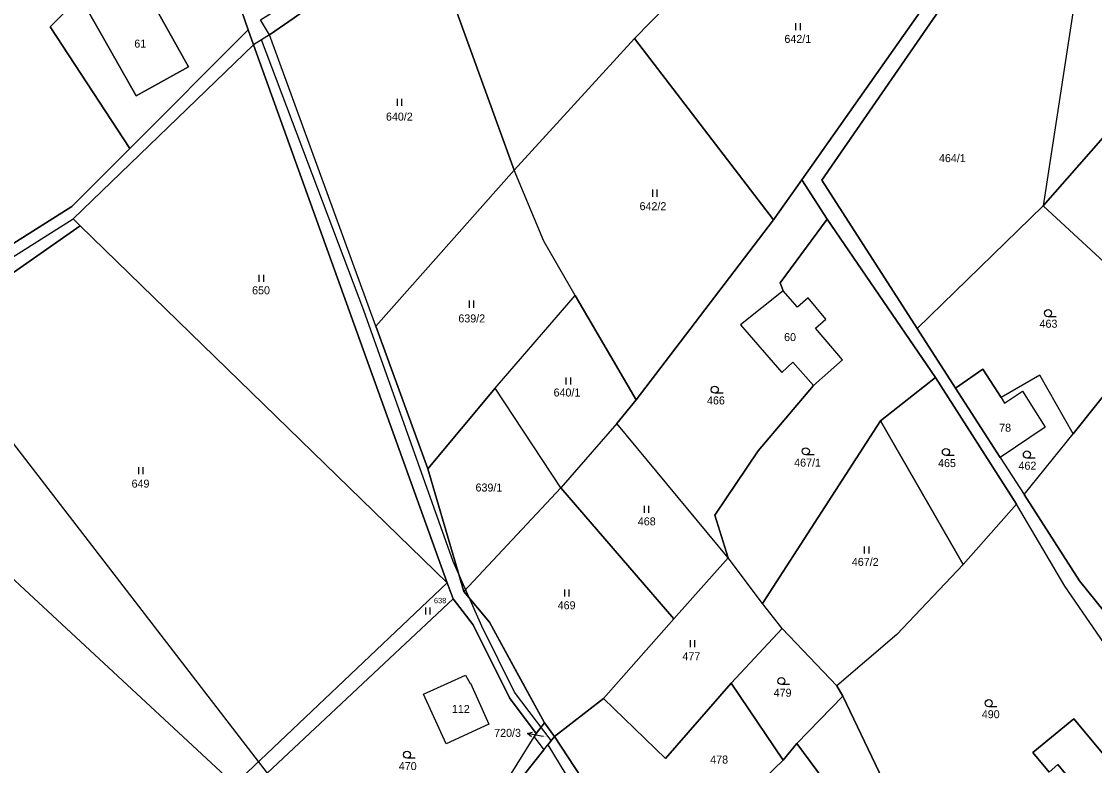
# Model space of a CAD drawing. Extents: x -590606 to -587796, y -1065936 to -1062515.
# Drawn here: x -589641.2 to -589413.2, y -1064918.8 to -1064760.8 of the extents above; entities that cross this region are included whole.
import ezdxf

# ---------------------------------------------------------------- set-up
doc = ezdxf.new("R2010")
doc.units = 0
for name, color, linetype in [('Cesty', 7, 'Continuous'), ('Parcela nároku', 7, 'Continuous'), ('Parcelní číslo', 7, 'Continuous'), ('Vnější obvod_ Studené', 7, 'Continuous'), ('Vrstva 1', 7, 'Continuous'), ('Vrstva 30', 7, 'Continuous'), ('Územní plán', 7, 'Continuous')]:
    doc.layers.add(name, color=color, linetype=linetype)

msp = doc.modelspace()

# ---------------------------------------------------------------- linework, layer by layer
at = {"layer": 'Cesty'}
msp.add_lwpolyline([(-589528.63, -1064913.52), (-589536.44, -1064903.23), (-589543.34, -1064889.26), (-589549.43, -1064875.48), (-589568.43, -1064822.17), (-589590.16, -1064764.72)], dxfattribs=at)
at = {"layer": 'Parcela nároku'}
for points in [[(-589522.89, -1064698.36), (-589513.75, -1064690.35), (-589497.56, -1064678.5), (-589496.63, -1064681.82), (-589511.03, -1064691.51), (-589528.63, -1064706.39), (-589554.07, -1064735.46), (-589571.42, -1064751.62), (-589583.26, -1064760.02), (-589588.45, -1064763.67), (-589590.38, -1064760.46), (-589573.06, -1064749.58), (-589560.8, -1064738.7), (-589530.19, -1064704.81)], [(-589378.38, -1064737.45), (-589411.5, -1064705.67), (-589425, -1064725.38), (-589416.09, -1064747.85), (-589424.1, -1064799.94), (-589411.31, -1064785.43), (-589390.57, -1064758.82)], [(-589530.55, -1064711.43), (-589504.08, -1064757.44), (-589510.92, -1064764.47), (-589536.47, -1064792.4), (-589552.16, -1064749.21), (-589553.84, -1064737.2)], [(-589605.54, -1064732.57), (-589618.13, -1064717.98), (-589627.72, -1064729.04), (-589662.24, -1064761.36), (-589694.16, -1064785.11), (-589664.99, -1064821.89), (-589630.44, -1064800.11), (-589618.14, -1064787.77), (-589635.08, -1064761.95), (-589628.69, -1064755.59), (-589628.92, -1064755.19), (-589627.45, -1064754.35)], [(-589473.46, -1064724.46), (-589449.38, -1064757.57), (-589475.36, -1064794.48), (-589481.42, -1064802.93), (-589510.92, -1064764.47), (-589504.08, -1064757.44)], [(-589447.12, -1064755.09), (-589425, -1064725.38), (-589416.09, -1064747.85), (-589424.1, -1064799.94), (-589450.87, -1064826.05), (-589471.15, -1064794.54), (-589445.45, -1064757.41)], [(-589593.02, -1064762.59), (-589597.63, -1064749.22), (-589605.54, -1064732.57), (-589627.45, -1064754.35), (-589617.78, -1064748.87), (-589613.71, -1064756.12), (-589605.65, -1064770.49), (-589616.76, -1064776.62), (-589624.91, -1064762.26), (-589628.69, -1064755.59), (-589635.08, -1064761.95), (-589618.14, -1064787.77)], [(-589583.26, -1064760.02), (-589571.42, -1064751.62), (-589554.07, -1064735.46), (-589553.84, -1064737.2), (-589552.16, -1064749.21), (-589536.47, -1064792.4), (-589565.9, -1064825.54), (-589588.45, -1064763.67)], [(-589605.65, -1064770.49), (-589613.71, -1064756.12), (-589617.78, -1064748.87), (-589627.45, -1064754.35), (-589628.92, -1064755.19), (-589628.69, -1064755.59), (-589624.91, -1064762.26), (-589616.76, -1064776.62)], [(-589593.02, -1064762.59), (-589618.14, -1064787.77), (-589630.44, -1064800.11), (-589664.99, -1064821.89), (-589669.05, -1064824.3), (-589667.75, -1064826.48), (-589630.17, -1064802.74), (-589591.88, -1064765.77)], [(-589550.69, -1064880.06), (-589591.88, -1064765.77), (-589630.17, -1064802.74), (-589628.67, -1064804.2)], [(-589510.92, -1064764.47), (-589481.42, -1064802.93), (-589510.57, -1064841.17), (-589523.5, -1064819.01), (-589530.21, -1064807.51), (-589536.47, -1064792.4)], [(-589411.31, -1064785.43), (-589424.1, -1064799.94), (-589398.19, -1064823.87), (-589385.83, -1064808.46)], [(-589523.5, -1064819.01), (-589530.21, -1064807.51), (-589536.47, -1064792.4), (-589565.9, -1064825.54), (-589554.84, -1064855.85), (-589540.51, -1064838.69)], [(-589479.64, -1064835.38), (-589477.29, -1064833.19), (-589472.89, -1064838.14), (-589484.61, -1064851.97), (-589493.85, -1064865.65), (-589491.05, -1064874.72), (-589514.68, -1064846.22), (-589510.57, -1064841.17), (-589481.42, -1064802.93), (-589475.36, -1064794.48), (-589469.95, -1064802.77), (-589480, -1064816.34), (-589479.3, -1064817.99), (-589488.43, -1064825.26)], [(-589424.1, -1064799.94), (-589398.19, -1064823.87), (-589417.74, -1064848.39), (-589424.79, -1064835.96), (-589433.05, -1064840.7), (-589436.92, -1064834.69), (-589442.72, -1064838.68), (-589450.87, -1064826.05)], [(-589672.56, -1064837.8), (-589664.19, -1064828.97), (-589628.67, -1064804.2), (-589550.69, -1064880.06), (-589595.93, -1064922.82), (-589688.26, -1064837.19), (-589677.04, -1064831.33)], [(-589630.17, -1064802.74), (-589628.67, -1064804.2), (-589664.19, -1064828.97), (-589672.56, -1064837.8), (-589677.04, -1064831.33), (-589667.75, -1064826.48)], [(-589469.95, -1064802.77), (-589447, -1064836.46), (-589458.66, -1064845.6), (-589483.72, -1064884.38), (-589491.05, -1064874.72), (-589493.85, -1064865.65), (-589484.61, -1064851.97), (-589472.89, -1064838.14), (-589466.74, -1064832.65), (-589472.45, -1064825.98), (-589470.28, -1064824.07), (-589474.03, -1064819.53), (-589476.31, -1064821.48), (-589479.3, -1064817.99), (-589480, -1064816.34)], [(-589466.74, -1064832.65), (-589472.45, -1064825.98), (-589470.28, -1064824.07), (-589474.03, -1064819.53), (-589476.31, -1064821.48), (-589479.3, -1064817.99), (-589488.43, -1064825.26), (-589479.64, -1064835.38), (-589477.29, -1064833.19), (-589472.89, -1064838.14)], [(-589540.51, -1064838.69), (-589523.5, -1064819.01), (-589510.57, -1064841.17), (-589514.68, -1064846.22), (-589526.55, -1064859.84)], [(-589417.74, -1064848.39), (-589398.19, -1064823.87), (-589382.87, -1064851.27), (-589357.44, -1064856.96), (-589360.23, -1064861.82), (-589364.23, -1064868.85), (-589369.41, -1064877.92), (-589371.23, -1064875.18), (-589374.55, -1064880.76), (-589389.82, -1064866.59), (-589402.24, -1064899.51), (-589405.49, -1064893.12), (-589416.34, -1064879.6), (-589428.15, -1064861.27)], [(-589458.66, -1064845.6), (-589447, -1064836.46), (-589429.73, -1064863.35), (-589441.1, -1064876.11)], [(-589433.05, -1064840.7), (-589432.28, -1064841.89), (-589428.45, -1064839.33), (-589423.69, -1064847), (-589433.24, -1064853.38), (-589442.72, -1064838.68), (-589436.92, -1064834.69)], [(-589424.79, -1064835.96), (-589433.05, -1064840.7), (-589432.28, -1064841.89), (-589428.45, -1064839.33), (-589423.69, -1064847), (-589433.24, -1064853.38), (-589428.15, -1064861.27), (-589417.74, -1064848.39)], [(-589738.8, -1064868.37), (-589722.06, -1064859.86), (-589695.94, -1064842.79), (-589696.42, -1064842.01), (-589688.26, -1064837.19), (-589595.93, -1064922.82), (-589621.92, -1064947.69), (-589643.25, -1064958.89)], [(-589540.51, -1064838.69), (-589554.84, -1064855.85), (-589547.18, -1064881.85), (-589526.55, -1064859.84)], [(-589458.66, -1064845.6), (-589441.1, -1064876.11), (-589455.18, -1064891.01), (-589467.9, -1064901.87), (-589479.54, -1064889.74), (-589483.72, -1064884.38)], [(-589491.05, -1064874.72), (-589514.68, -1064846.22), (-589526.55, -1064859.84), (-589502.56, -1064887.68)], [(-589502.56, -1064887.68), (-589526.55, -1064859.84), (-589547.18, -1064881.85), (-589541.76, -1064888.37), (-589530.03, -1064909.73), (-589527.95, -1064912.63), (-589517.52, -1064904.58)], [(-589419.51, -1064880.71), (-589429.73, -1064863.35), (-589441.1, -1064876.11), (-589455.18, -1064891.01), (-589467.9, -1064901.87), (-589466.69, -1064904.1), (-589451.25, -1064936.39), (-589448.63, -1064940.01), (-589428.23, -1064968.24), (-589418.35, -1064953.57), (-589406.51, -1064936.87), (-589411.18, -1064930.48), (-589420.99, -1064918.63), (-589422.85, -1064920.26), (-589426.28, -1064916.08), (-589417.57, -1064908.93), (-589404.77, -1064924.29), (-589403.91, -1064923.64), (-589400.68, -1064928.65), (-589394.5, -1064919.94), (-589399.91, -1064912.39), (-589408.85, -1064896.13)], [(-589479.54, -1064889.74), (-589483.72, -1064884.38), (-589491.05, -1064874.72), (-589502.56, -1064887.68), (-589517.52, -1064904.58), (-589504.34, -1064917.35), (-589490.4, -1064901.33)], [(-589643.25, -1064958.89), (-589718.4, -1064982.65), (-589738.86, -1064988.82), (-589792.56, -1065010.99), (-589790.16, -1065012.34), (-589739.56, -1064991.1), (-589640.21, -1064959.48), (-589620.7, -1064948.96), (-589616.14, -1064944.82), (-589588.94, -1064920.46), (-589549.47, -1064883.45), (-589550.69, -1064880.06), (-589595.93, -1064922.82), (-589621.92, -1064947.69)], [(-589531.78, -1064912.02), (-589537.45, -1064904.41), (-589545.23, -1064888.95), (-589549.47, -1064883.45), (-589588.94, -1064920.46), (-589561.54, -1064947.84), (-589554.15, -1064941.61), (-589543.1, -1064930.15), (-589532.21, -1064912.7)], [(-589467.9, -1064901.87), (-589479.54, -1064889.74), (-589490.4, -1064901.33), (-589479.31, -1064917.7), (-589476.4, -1064914.15), (-589466.69, -1064904.1)], [(-589555.78, -1064903.64), (-589550.57, -1064901.31), (-589546.82, -1064899.63), (-589545.82, -1064901.39), (-589545.73, -1064901.35), (-589541.86, -1064910.05), (-589550.95, -1064914.2)], [(-589550.95, -1064914.2), (-589555.78, -1064903.64), (-589550.57, -1064901.31), (-589546.82, -1064899.63), (-589545.82, -1064901.39), (-589545.73, -1064901.35), (-589541.86, -1064910.05)], [(-589479.31, -1064917.7), (-589490.4, -1064901.33), (-589504.34, -1064917.35), (-589517.52, -1064904.58), (-589527.95, -1064912.63), (-589515.22, -1064931.98), (-589508.2, -1064945.52)], [(-589448.63, -1064940.01), (-589451.25, -1064936.39), (-589466.69, -1064904.1), (-589476.4, -1064914.15), (-589456.4, -1064941.16), (-589454.23, -1064944.2)], [(-589530.03, -1064909.73), (-589531.78, -1064912.02), (-589532.21, -1064912.7), (-589530.19, -1064915.51), (-589529.31, -1064914.41), (-589527.95, -1064912.63)], [(-589403.91, -1064923.64), (-589404.77, -1064924.29), (-589417.57, -1064908.93), (-589426.28, -1064916.08), (-589422.85, -1064920.26), (-589420.99, -1064918.63), (-589411.18, -1064930.48), (-589406.51, -1064936.87), (-589400.68, -1064928.65)], [(-589538.71, -1064926.19), (-589537.53, -1064968.54), (-589540.75, -1064971.67), (-589541.18, -1064963.89), (-589543.1, -1064930.15), (-589532.21, -1064912.7), (-589530.19, -1064915.51)], [(-589451.81, -1065036.64), (-589454.82, -1065029.46), (-589466.26, -1065019.11), (-589474.4, -1065009.98), (-589483.68, -1064996.15), (-589491.55, -1064979.3), (-589492.91, -1064977.48), (-589494.4, -1064974.29), (-589508.2, -1064945.52), (-589515.22, -1064931.98), (-589527.95, -1064912.63), (-589529.31, -1064914.41), (-589518.09, -1064932.98), (-589512.24, -1064943.97), (-589510.53, -1064947.19), (-589495.32, -1064979.07), (-589494.1, -1064981.46), (-589486.57, -1064996.85), (-589476.59, -1065010.77), (-589454.84, -1065036.64), (-589446.88, -1065047.17), (-589438.79, -1065057.06), (-589428.09, -1065070.14), (-589425.07, -1065067.02)], [(-589479.31, -1064917.7), (-589508.2, -1064945.52), (-589494.4, -1064974.29), (-589480.65, -1064963.95), (-589454.23, -1064944.2), (-589456.4, -1064941.16), (-589476.4, -1064914.15)]]:
    msp.add_lwpolyline(points, close=True, dxfattribs=at)
for points in [[(-589597.63, -1064749.22), (-589593.02, -1064762.59), (-589591.88, -1064765.77), (-589550.69, -1064880.06), (-589549.47, -1064883.45), (-589545.23, -1064888.95), (-589537.45, -1064904.41), (-589531.78, -1064912.02), (-589530.03, -1064909.73), (-589541.76, -1064888.37), (-589547.18, -1064881.85), (-589554.84, -1064855.85), (-589565.9, -1064825.54), (-589588.45, -1064763.67), (-589590.38, -1064760.46)], [(-589408.85, -1064896.13), (-589419.51, -1064880.71), (-589429.73, -1064863.35), (-589447, -1064836.46), (-589469.95, -1064802.77), (-589475.36, -1064794.48), (-589449.38, -1064757.57)], [(-589445.45, -1064757.41), (-589471.15, -1064794.54), (-589450.87, -1064826.05), (-589442.72, -1064838.68), (-589433.24, -1064853.38), (-589428.15, -1064861.27), (-589416.34, -1064879.6), (-589405.49, -1064893.12)]]:
    msp.add_lwpolyline(points, dxfattribs=at)
at = {"layer": 'Parcelní číslo'}
for p, q in [((-589530.72, -1064912.58), (-589533.67, -1064912.02)), ((-589530.23, -1064912.67), (-589530.72, -1064912.58))]:
    msp.add_line(p, q, dxfattribs=at)
msp.add_lwpolyline([(-589532.78, -1064912.7), (-589533.67, -1064912.02), (-589532.59, -1064911.71)], dxfattribs=at)
at = {"layer": 'Vnější obvod_ Studené'}
for p, q in [((-589635.08, -1064761.95), (-589628.69, -1064755.59)), ((-589618.14, -1064787.77), (-589635.08, -1064761.95)), ((-589593.02, -1064762.59), (-589618.14, -1064787.77)), ((-589591.88, -1064765.77), (-589593.02, -1064762.59)), ((-589588.45, -1064763.67), (-589591.88, -1064765.77)), ((-589565.9, -1064825.54), (-589588.45, -1064763.67)), ((-589554.84, -1064855.85), (-589565.9, -1064825.54)), ((-589547.18, -1064881.85), (-589554.84, -1064855.85)), ((-589541.76, -1064888.37), (-589547.18, -1064881.85)), ((-589588.94, -1064920.46), (-589549.47, -1064883.45)), ((-589549.47, -1064883.45), (-589545.23, -1064888.95)), ((-589545.23, -1064888.95), (-589537.45, -1064904.41)), ((-589535.9, -1064899.05), (-589541.76, -1064888.37)), ((-589530.03, -1064909.73), (-589535.9, -1064899.05)), ((-589537.45, -1064904.41), (-589531.78, -1064912.02)), ((-589527.95, -1064912.63), (-589530.03, -1064909.73)), ((-589531.78, -1064912.02), (-589532.21, -1064912.7)), ((-589532.21, -1064912.7), (-589530.19, -1064915.51)), ((-589529.31, -1064914.41), (-589527.95, -1064912.63)), ((-589530.19, -1064915.51), (-589529.31, -1064914.41))]:
    msp.add_line(p, q, dxfattribs=at)
at = {"layer": 'Vrstva 1'}
msp.add_lwpolyline([(-589538.71, -1064926.19), (-589530.19, -1064915.51), (-589529.31, -1064914.41), (-589518.09, -1064932.98), (-589512.24, -1064943.97), (-589537.53, -1064968.54)], close=True, dxfattribs=at)
at = {"layer": 'Vrstva 30'}
for p, q in [((-589476.69, -1064761.19), (-589476.69, -1064762.69)), ((-589475.67, -1064762.69), (-589475.67, -1064761.19)), ((-589561.35, -1064777.22), (-589561.35, -1064778.72)), ((-589560.33, -1064778.72), (-589560.33, -1064777.22)), ((-589507.09, -1064796.54), (-589507.09, -1064798.04)), ((-589506.07, -1064798.04), (-589506.07, -1064796.54)), ((-589590.7, -1064814.61), (-589590.7, -1064816.11)), ((-589589.68, -1064816.11), (-589589.68, -1064814.61)), ((-589546.07, -1064820.1), (-589546.07, -1064821.6)), ((-589545.05, -1064821.6), (-589545.05, -1064820.1)), ((-589421.3, -1064823.52), (-589423.05, -1064823.52)), ((-589525.49, -1064836.39), (-589525.49, -1064837.89)), ((-589524.46, -1064837.89), (-589524.46, -1064836.39)), ((-589492.11, -1064839.76), (-589493.86, -1064839.76)), ((-589472.77, -1064852.84), (-589474.52, -1064852.84)), ((-589443.01, -1064853), (-589444.76, -1064853)), ((-589425.8, -1064853.53), (-589427.55, -1064853.53)), ((-589616.33, -1064855.46), (-589616.33, -1064856.96)), ((-589615.31, -1064856.96), (-589615.31, -1064855.46)), ((-589508.88, -1064863.69), (-589508.88, -1064865.19)), ((-589507.85, -1064865.19), (-589507.85, -1064863.69)), ((-589462.09, -1064872.3), (-589462.09, -1064873.8)), ((-589461.07, -1064873.8), (-589461.07, -1064872.3)), ((-589525.82, -1064881.43), (-589525.82, -1064882.93)), ((-589524.8, -1064882.93), (-589524.8, -1064881.43)), ((-589555.33, -1064885.27), (-589555.33, -1064886.77)), ((-589554.31, -1064886.77), (-589554.31, -1064885.27)), ((-589499.11, -1064892.21), (-589499.11, -1064893.71)), ((-589498.08, -1064893.71), (-589498.08, -1064892.21)), ((-589477.96, -1064901.63), (-589479.71, -1064901.63)), ((-589433.91, -1064906.33), (-589435.66, -1064906.33)), ((-589557.5, -1064917.27), (-589559.25, -1064917.27))]:
    msp.add_line(p, q, dxfattribs=at)
for centre in [(-589423.05, -1064822.77), (-589493.86, -1064839.01), (-589474.52, -1064852.09), (-589444.76, -1064852.25), (-589427.55, -1064852.78), (-589479.71, -1064900.88), (-589435.66, -1064905.58), (-589559.25, -1064916.52)]:
    msp.add_circle(centre, 0.75, dxfattribs=at)
at = {"layer": 'Územní plán'}
msp.add_line((-589664.99, -1064821.89), (-589588.94, -1064920.46), dxfattribs=at)

# ---------------------------------------------------------------- texts
at = {"layer": 'Parcela nároku'}
for s, height, p in [('642/1', 1.7, (-589479.07, -1064765.38)), ('61', 1.7, (-589617.19, -1064766.38)), ('640/2', 1.7, (-589563.72, -1064781.88)), ('464/1', 1.7, (-589446.23, -1064790.7)), ('642/2', 1.7, (-589509.84, -1064800.9)), ('650', 1.7, (-589592.16, -1064818.76)), ('639/2', 1.7, (-589548.34, -1064824.73)), ('463', 1.7, (-589424.86, -1064825.86)), ('60', 1.7, (-589479.13, -1064828.69)), ('640/1', 1.7, (-589528.11, -1064840.46)), ('466', 1.7, (-589495.51, -1064842.15)), ('78', 1.7, (-589433.44, -1064847.93)), ('467/1', 1.7, (-589476.99, -1064855.35)), ('465', 1.7, (-589446.42, -1064855.45)), ('462', 1.7, (-589429.33, -1064856)), ('649', 1.7, (-589617.77, -1064859.81)), ('639/1', 1.7, (-589544.69, -1064860.64)), ('468', 1.7, (-589510.21, -1064867.82)), ('467/2', 1.7, (-589464.74, -1064876.43)), ('638', 1.14, (-589553.53, -1064884.36)), ('469', 1.7, (-589527.24, -1064885.64)), ('477', 1.7, (-589500.73, -1064896.46)), ('479', 1.7, (-589481.35, -1064904.2)), ('112', 1.7, (-589549.72, -1064907.66)), ('490', 1.7, (-589437.13, -1064908.78)), ('720/3', 0.1, (-589530.23, -1064912.67)), ('470', 1.7, (-589560.99, -1064919.78)), ('478', 1.7, (-589494.83, -1064918.4))]:
    msp.add_text(s, height=height, dxfattribs=at).set_placement(p)
at = {"layer": 'Parcelní číslo'}
msp.add_text('720/3', height=1.7, dxfattribs=at).set_placement((-589540.73, -1064912.73))

doc.saveas('drawing.dxf')
